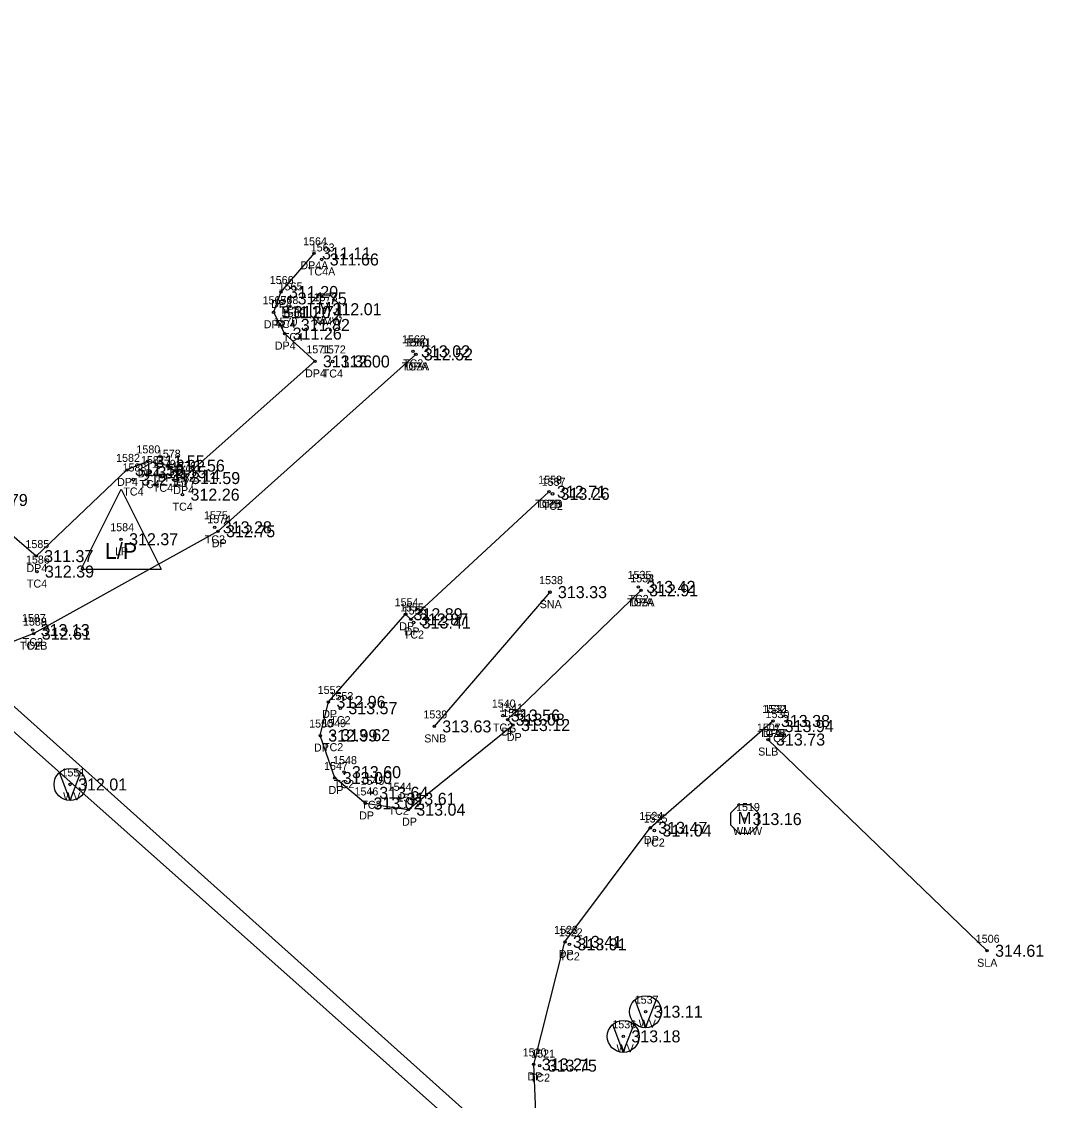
# Model space of a CAD drawing. Extents: x 1970076 to 1971136, y 803126 to 804215.
# Drawn here: x 1970942 to 1971069.6, y 803243.6 to 803378.3 of the extents above; entities that cross this region are included whole.
import ezdxf

# ---------------------------------------------------------------- set-up
doc = ezdxf.new("R2010")
doc.units = 0
for name, color, linetype in [('RD_EX_BldgApp', 7, 'Continuous'), ('RD_EX_BldgApp_txCode', 7, 'Continuous'), ('RD_EX_Conc', 7, 'Continuous'), ('RD_EX_Conc_txCode', 7, 'Continuous'), ('RD_EX_DR_Pipe', 7, 'Continuous'), ('RD_EX_Driveway', 7, 'Continuous'), ('RD_EX_Driveway_txCode', 7, 'Continuous'), ('RD_EX_Misc_txCode', 7, 'Continuous'), ('RD_EX_SU_H2O', 7, 'Continuous'), ('RD_EX_TX_BldgApp_ELEV', 7, 'Continuous'), ('RD_EX_TX_Conc_ELEV', 7, 'Continuous'), ('RD_EX_TX_Driveway_ELEV', 7, 'Continuous'), ('RD_EX_TX_Misc_ELEV', 7, 'Continuous'), ('RD_EX_TX_UT_ELEV', 7, 'Continuous'), ('RD_EX_TX_VEG_ELEV', 7, 'Continuous'), ('RD_EX_UT', 7, 'Continuous'), ('RD_EX_UT_txCode', 7, 'Continuous'), ('RD_EX_VEG', 7, 'Continuous'), ('RD_EX_VEG_txCode', 7, 'Continuous'), ('RD_SMD_Locator', 7, 'Continuous')]:
    doc.layers.add(name, color=color, linetype=linetype)

msp = doc.modelspace()

# ---------------------------------------------------------------- linework, layer by layer
at = {"layer": 'RD_EX_BldgApp'}
msp.add_line((1971007.94, 803307.05), (1970993.5, 803290.28), dxfattribs=at)
at = {"layer": 'RD_EX_Conc'}
msp.add_lwpolyline([(1971009.74, 803224.24), (1971010.01, 803224.85), (1971010.25, 803225.52), (1971006.59, 803233.99), (1970934.65, 803298.46), (1970929.07, 803297.51), (1970928.19, 803297.32), (1970927.5, 803297.02)], dxfattribs=at)
at = {"layer": 'RD_EX_DR_Pipe'}
msp.add_line((1971022.85, 803216.85), (1970817.34, 803399.52), dxfattribs=at)
at = {"layer": 'RD_EX_Driveway'}
for points in [[(1970978.49, 803349.37), (1970974.36, 803344.54), (1970973.43, 803342.01), (1970974.82, 803339.34), (1970978.6, 803335.88), (1970962.13, 803321.3), (1970960.21, 803322.85), (1970957.7, 803323.38), (1970955.12, 803322.32), (1970943.79, 803311.55), (1970935.6, 803318.56), (1970864.97, 803381.97), (1970876.89, 803395.59), (1970878.3, 803398.67), (1970875.35, 803402.77), (1970871.74, 803402.91), (1970869.45, 803401.14), (1970846.9, 803376.22)], [(1970991.2, 803336.74), (1970966.5, 803314.66), (1970943.49, 803301.87), (1970934.65, 803298.46)], [(1971019.33, 803307.28), (1971002.67, 803291.13), (1971003.34, 803290.45), (1970990.26, 803279.88), (1970984.91, 803280.66), (1970981.08, 803283.84), (1970979.26, 803289.14), (1970980.29, 803293.34), (1970989.91, 803304.29), (1970990.58, 803303.64), (1971007.82, 803319.59)], [(1971006.59, 803233.99), (1971006.48, 803235.13), (1971005.93, 803248.07), (1971009.82, 803263.37), (1971020.47, 803277.61), (1971035.79, 803290.96)]]:
    msp.add_lwpolyline(points, dxfattribs=at)
at = {"layer": 'RD_EX_SU_H2O'}
for points in [[(1970981.54, 803341.66), (1970981.54, 803343.12), (1970980.52, 803344.14), (1970979.06, 803344.14), (1970978.04, 803343.12), (1970978.04, 803341.66), (1970979.06, 803340.64), (1970980.52, 803340.64)], [(1971034, 803277.99), (1971034, 803279.44), (1971032.97, 803280.47), (1971031.52, 803280.47), (1971030.5, 803279.44), (1971030.5, 803277.99), (1971031.52, 803276.96), (1971032.97, 803276.96)]]:
    msp.add_lwpolyline(points, close=True, dxfattribs=at)
at = {"layer": 'RD_EX_UT'}
for p, q in [((1970949.39, 803309.93), (1970954.39, 803319.93)), ((1970954.39, 803319.93), (1970959.39, 803309.93)), ((1970949.39, 803309.93), (1970959.39, 803309.93)), ((1970948.02, 803281.04), (1970946.71, 803284.52)), ((1970948.02, 803281.04), (1970949.34, 803284.49)), ((1971019.89, 803252.65), (1971018.58, 803256.14)), ((1971019.89, 803252.65), (1971021.21, 803256.1)), ((1971017.11, 803249.58), (1971015.81, 803253.06)), ((1971017.11, 803249.58), (1971018.44, 803253.02))]:
    msp.add_line(p, q, dxfattribs=at)
for centre in [(1970948.02, 803283.03), (1971019.89, 803254.65), (1971017.11, 803251.57)]:
    msp.add_circle(centre, 2, dxfattribs=at)
at = {"layer": 'RD_EX_VEG'}
msp.add_line((1971062.54, 803262.26), (1971035.18, 803288.64), dxfattribs=at)
at = {"layer": 'RD_SMD_Locator'}
for centre in [(1970978.49, 803349.37), (1970979.45, 803348.6), (1970974.36, 803344.54), (1970975.44, 803343.74), (1970979.79, 803342.39), (1970973.43, 803342.01), (1970974.92, 803342.04), (1970975.83, 803340.42), (1970974.82, 803339.34), (1970990.84, 803337.13), (1970991.2, 803336.74), (1970991.2, 803336.74), (1970978.6, 803335.88), (1970980.81, 803335.86), (1970957.7, 803323.38), (1970955.12, 803322.32), (1970957.93, 803322.04), (1970960.21, 803322.85), (1970955.92, 803321.12), (1970959.6, 803321.58), (1970962.13, 803321.3), (1970962.06, 803319.23), (1971007.82, 803319.59), (1971007.82, 803319.59), (1971008.27, 803319.33), (1970966.09, 803315.15), (1970966.5, 803314.66), (1970954.39, 803313.66), (1970943.79, 803311.55), (1970943.88, 803309.62), (1971007.94, 803307.05), (1971018.99, 803307.71), (1971019.33, 803307.28), (1971019.33, 803307.28), (1970989.91, 803304.29), (1970990.58, 803303.64), (1970990.93, 803303.26), (1970943.35, 803302.31), (1970943.49, 803301.87), (1970943.49, 803301.87), (1970980.29, 803293.34), (1970981.77, 803292.56), (1971002.07, 803291.64), (1971002.67, 803291.13), (1971035.79, 803290.96), (1971035.79, 803290.96), (1970993.5, 803290.28), (1971003.34, 803290.45), (1971036.26, 803290.32), (1970979.26, 803289.14), (1970980.86, 803289.19), (1971035.18, 803288.64), (1970982.22, 803284.57), (1970948.02, 803283.03), (1970981.08, 803283.84), (1970985.63, 803281.99), (1970984.91, 803280.66), (1970989.03, 803281.24), (1970990.26, 803279.88), (1971020.47, 803277.61), (1971032.25, 803278.71), (1971021, 803277.28), (1971009.82, 803263.37), (1971010.39, 803263.06), (1971062.54, 803262.26), (1971019.89, 803254.65), (1971017.11, 803251.57), (1971005.93, 803248.07), (1971006.67, 803247.91)]:
    msp.add_circle(centre, 0.15, dxfattribs=at)

# ---------------------------------------------------------------- texts
at = {"layer": 'RD_EX_BldgApp_txCode'}
for s, p in [('1538', (1971006.6, 803308.05)), ('SNA', (1971006.67, 803305.05)), ('1539', (1970992.15, 803291.28)), ('SNB', (1970992.25, 803288.28))]:
    msp.add_text(s, height=1, dxfattribs=at).set_placement(p)
at = {"layer": 'RD_EX_Conc_txCode'}
for s, p in [('1563', (1970978.08, 803349.6)), ('TC4A', (1970977.72, 803346.6)), ('1565', (1970974.07, 803344.74)), ('1568', (1970973.55, 803343.04)), ('TC4', (1970974.19, 803341.74)), ('1569', (1970974.46, 803341.42)), ('TC4', (1970973.67, 803340.04)), ('TC4', (1970974.59, 803338.42)), ('1562', (1970989.47, 803338.13)), ('1561', (1970990.11, 803337.74)), ('1572', (1970979.47, 803336.86)), ('TC2A', (1970989.46, 803334.74)), ('TC2', (1970989.6, 803335.13)), ('TC4', (1970979.57, 803333.86)), ('1581', (1970956.87, 803323.04)), ('1579', (1970958.25, 803322.58)), ('1583', (1970954.57, 803322.12)), ('TC4', (1970956.69, 803320.04)), ('1577', (1970960.71, 803320.23)), ('1558', (1971006.48, 803320.59)), ('1557', (1971006.92, 803320.33)), ('TC4', (1970954.67, 803319.12)), ('TC4', (1970958.36, 803319.58)), ('TC4', (1970960.82, 803317.23)), ('TC2B', (1971006.11, 803317.59)), ('TC2', (1971007.03, 803317.33)), ('1575', (1970964.74, 803316.15)), ('TC2', (1970964.84, 803313.15)), ('1586', (1970942.51, 803310.62)), ('TC4', (1970942.63, 803307.62)), ('1535', (1971017.65, 803308.71)), ('1534', (1971017.98, 803308.28)), ('TC2A', (1971017.6, 803305.28)), ('TC2', (1971017.75, 803305.71)), ('1556', (1970989.56, 803304.26)), ('1587', (1970942.01, 803303.31)), ('1589', (1970942.14, 803302.87)), ('TC2', (1970989.69, 803301.26)), ('TC2B', (1970941.77, 803299.87)), ('TC2', (1970942.11, 803300.31)), ('1553', (1970980.42, 803293.56)), ('1540', (1971000.69, 803292.64)), ('1531', (1971034.73, 803291.96)), ('1549', (1970979.51, 803290.19)), ('TC2', (1970980.52, 803290.56)), ('1530', (1971034.87, 803291.32)), ('TC2', (1971000.83, 803289.64)), ('TC2B', (1971034.08, 803288.96)), ('TC2', (1971035.01, 803288.32)), ('TC2', (1970979.61, 803287.19)), ('1548', (1970980.87, 803285.57)), ('TC2', (1970980.97, 803282.57)), ('1545', (1970984.29, 803282.99)), ('1544', (1970987.69, 803282.24)), ('TC2', (1970984.39, 803279.99)), ('TC2', (1970987.79, 803279.24)), ('1525', (1971019.66, 803278.28)), ('TC2', (1971019.76, 803275.28)), ('1522', (1971009.05, 803264.06)), ('TC2', (1971009.15, 803261.06)), ('1521', (1971005.61, 803248.91)), ('TC2', (1971005.43, 803245.91))]:
    msp.add_text(s, height=1, dxfattribs=at).set_placement(p)
at = {"layer": 'RD_EX_Driveway_txCode'}
for s, p in [('1564', (1970977.12, 803350.37)), ('DP4A', (1970976.78, 803347.37)), ('1566', (1970972.96, 803345.54)), ('1567', (1970972.06, 803343.01)), ('DP4', (1970973.13, 803342.54)), ('DP4', (1970972.21, 803340.01)), ('1570', (1970973.44, 803340.34)), ('DP4', (1970973.59, 803337.34)), ('1560', (1970989.79, 803337.74)), ('1571', (1970977.53, 803336.88)), ('DPA', (1970989.93, 803334.74)), ('DP4', (1970977.37, 803333.88)), ('1580', (1970956.31, 803324.38)), ('1578', (1970958.86, 803323.85)), ('1582', (1970953.77, 803323.32)), ('DP4', (1970956.47, 803321.38)), ('1576', (1970960.76, 803322.3)), ('DP4', (1970953.89, 803320.32)), ('DP4', (1970958.98, 803320.85)), ('1559', (1971006.48, 803320.59)), ('DP4', (1970960.91, 803319.3)), ('DPB', (1971006.57, 803317.59)), ('1574', (1970965.15, 803315.66)), ('1585', (1970942.45, 803312.55)), ('DP', (1970965.72, 803312.66)), ('DP4', (1970942.57, 803309.55)), ('1533', (1971017.98, 803308.28)), ('1554', (1970988.56, 803305.29)), ('DPA', (1971018.06, 803305.28)), ('1555', (1970989.23, 803304.64)), ('1588', (1970942.14, 803302.87)), ('DP', (1970989.13, 803302.29)), ('DP', (1970989.8, 803301.64)), ('DP', (1970942.71, 803299.87)), ('1552', (1970978.95, 803294.34)), ('1541', (1971001.61, 803292.13)), ('1542', (1971002, 803291.45)), ('1532', (1971034.45, 803291.96)), ('1550', (1970977.88, 803290.14)), ('DP', (1970979.51, 803291.34)), ('DP', (1971001.89, 803289.13)), ('DPB', (1971034.54, 803288.96)), ('DP', (1971002.56, 803288.45)), ('DP', (1970978.48, 803287.14)), ('1547', (1970979.74, 803284.84)), ('DP', (1970980.3, 803281.84)), ('1546', (1970983.54, 803281.66)), ('1543', (1970988.92, 803280.88)), ('DP', (1970984.13, 803278.66)), ('DP', (1970989.48, 803277.88)), ('1524', (1971019.13, 803278.61)), ('DP', (1971019.69, 803275.61)), ('1523', (1971008.47, 803264.37)), ('DP', (1971009.04, 803261.37)), ('1520', (1971004.55, 803249.07)), ('DP', (1971005.15, 803246.07))]:
    msp.add_text(s, height=1, dxfattribs=at).set_placement(p)
at = {"layer": 'RD_EX_Misc_txCode'}
for s, p in [('1573', (1970978.44, 803343.39)), ('WMW', (1970978.35, 803340.39)), ('1519', (1971031.19, 803279.71)), ('WMW', (1971030.81, 803276.71))]:
    msp.add_text(s, height=1, dxfattribs=at).set_placement(p)
at = {"layer": 'RD_EX_SU_H2O'}
for p in [(1970978.96, 803341.78), (1971031.41, 803278.11)]:
    msp.add_text('M', height=1.5, dxfattribs=at).set_placement(p)
at = {"layer": 'RD_EX_TX_BldgApp_ELEV'}
for s, p in [('313.33', (1971008.94, 803306.3)), ('313.63', (1970994.5, 803289.53))]:
    msp.add_text(s, height=1.5, dxfattribs=at).set_placement(p)
at = {"layer": 'RD_EX_TX_Conc_ELEV'}
for s, p in [('311.66', (1970980.45, 803347.85)), ('311.75', (1970976.44, 803342.99)), ('311.74', (1970975.92, 803341.29)), ('311.82', (1970976.83, 803339.67)), ('313.02', (1970991.84, 803336.38)), ('312.52', (1970992.2, 803335.99)), ('312.00', (1970981.81, 803335.11)), ('312.15', (1970958.93, 803321.29)), ('312.14', (1970960.6, 803320.83)), ('312.17', (1970956.92, 803320.37)), ('312.26', (1970963.06, 803318.48)), ('312.71', (1971008.82, 803318.84)), ('313.26', (1971009.27, 803318.58)), ('313.28', (1970967.09, 803314.4)), ('312.39', (1970944.88, 803308.87)), ('313.42', (1971019.99, 803306.96)), ('312.91', (1971020.33, 803306.53)), ('313.41', (1970991.93, 803302.51)), ('313.13', (1970944.35, 803301.56)), ('312.61', (1970944.49, 803301.12)), ('313.57', (1970982.77, 803291.81)), ('313.56', (1971003.07, 803290.89)), ('313.38', (1971036.79, 803290.21)), ('313.94', (1971037.26, 803289.57)), ('313.62', (1970981.86, 803288.44)), ('313.60', (1970983.22, 803283.82)), ('313.64', (1970986.63, 803281.24)), ('313.61', (1970990.03, 803280.49)), ('314.04', (1971022, 803276.53)), ('313.91', (1971011.39, 803262.31)), ('313.75', (1971007.67, 803247.16))]:
    msp.add_text(s, height=1.5, dxfattribs=at).set_placement(p)
at = {"layer": 'RD_EX_TX_Driveway_ELEV'}
for s, p in [('311.11', (1970979.49, 803348.62)), ('311.20', (1970975.36, 803343.79)), ('311.20', (1970974.43, 803341.26)), ('311.26', (1970975.82, 803338.59)), ('312.52', (1970992.2, 803335.99)), ('311.36', (1970979.6, 803335.13)), ('311.55', (1970958.7, 803322.63)), ('311.56', (1970961.21, 803322.1)), ('311.58', (1970956.12, 803321.57)), ('311.59', (1970963.13, 803320.55)), ('311.79', (1970936.6, 803317.81)), ('312.71', (1971008.82, 803318.84)), ('312.75', (1970967.5, 803313.91)), ('311.37', (1970944.79, 803310.8)), ('312.91', (1971020.33, 803306.53)), ('312.89', (1970990.91, 803303.54)), ('312.87', (1970991.58, 803302.89)), ('312.61', (1970944.49, 803301.12)), ('312.96', (1970981.29, 803292.59)), ('313.08', (1971003.67, 803290.38)), ('313.12', (1971004.34, 803289.7)), ('313.38', (1971036.79, 803290.21)), ('312.99', (1970980.26, 803288.39)), ('313.00', (1970982.08, 803283.09)), ('313.02', (1970985.91, 803279.91)), ('313.04', (1970991.26, 803279.13)), ('313.47', (1971021.47, 803276.86)), ('313.41', (1971010.82, 803262.62)), ('313.21', (1971006.93, 803247.32))]:
    msp.add_text(s, height=1.5, dxfattribs=at).set_placement(p)
at = {"layer": 'RD_EX_TX_Misc_ELEV'}
for s, p in [('312.01', (1970980.79, 803341.64)), ('313.16', (1971033.25, 803277.96))]:
    msp.add_text(s, height=1.5, dxfattribs=at).set_placement(p)
at = {"layer": 'RD_EX_TX_UT_ELEV'}
for s, p in [('312.37', (1970955.39, 803312.91)), ('312.01', (1970949.02, 803282.28)), ('313.11', (1971020.89, 803253.9)), ('313.18', (1971018.11, 803250.82))]:
    msp.add_text(s, height=1.5, dxfattribs=at).set_placement(p)
at = {"layer": 'RD_EX_TX_VEG_ELEV'}
for s, p in [('313.73', (1971036.18, 803287.89)), ('314.61', (1971063.54, 803261.51))]:
    msp.add_text(s, height=1.5, dxfattribs=at).set_placement(p)
at = {"layer": 'RD_EX_UT'}
msp.add_text('L/P', height=2, dxfattribs=at).set_placement((1970952.38, 803311.21))
at = {"layer": 'RD_EX_UT_txCode'}
for s, p in [('1584', (1970953.04, 803314.66)), ('LP', (1970953.63, 803311.66)), ('1551', (1970946.95, 803284.03)), ('WV', (1970947.16, 803281.03)), ('1537', (1971018.54, 803255.65)), ('1536', (1971015.74, 803252.57)), ('WV', (1971019.03, 803252.65)), ('WV', (1971016.26, 803249.57))]:
    msp.add_text(s, height=1, dxfattribs=at).set_placement(p)
at = {"layer": 'RD_EX_VEG_txCode'}
for s, p in [('1507', (1971033.79, 803289.64)), ('SLB', (1971033.95, 803286.64)), ('1506', (1971061.13, 803263.26)), ('SLA', (1971061.3, 803260.26))]:
    msp.add_text(s, height=1, dxfattribs=at).set_placement(p)

doc.saveas('drawing.dxf')
